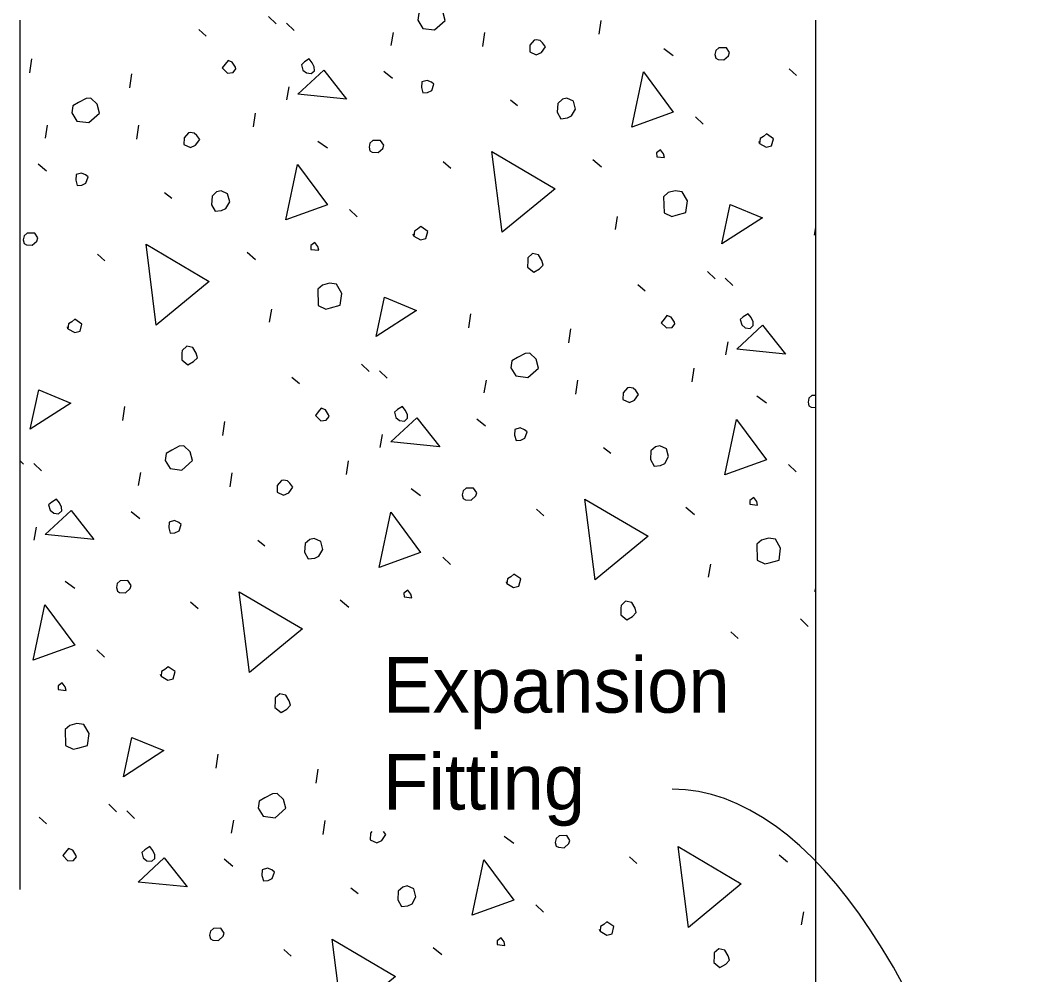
# Model space of a CAD drawing. Extents: x 0 to 30.8, y 0 to 21.2.
# Drawn here: x 22.627 to 25.369, y 14.241 to 16.841 of the extents above; entities that cross this region are included whole.
import ezdxf

# ---------------------------------------------------------------- set-up
doc = ezdxf.new("R2010")
doc.units = 0
for name, color, linetype in [('Dimension', 7, 'Continuous'), ('Miscellaneous', 7, 'Continuous'), ('SupstrConc', 7, 'Continuous')]:
    doc.layers.add(name, color=color, linetype=linetype)

msp = doc.modelspace()

# ---------------------------------------------------------------- linework, layer by layer
at = {"layer": 'Dimension'}
msp.add_ellipse((24.3864, 11.0659), major_axis=(-0.0172, -3.681), ratio=0.331804, start_param=2.220726, end_param=3.141608, dxfattribs=at)
at = {"layer": 'Miscellaneous'}
for p, q in [((23.3036, 16.8513), (23.3246, 16.8311)), ((24.2044, 16.8028), (24.2098, 16.8405)), ((23.1138, 16.816), (23.1341, 16.7981)), ((23.3524, 16.8333), (23.3734, 16.8131)), ((23.6379, 16.7726), (23.644, 16.8079)), ((23.8872, 16.7696), (23.8926, 16.8073)), ((24.3803, 16.7645), (24.4061, 16.7455)), ((22.6537, 16.6979), (22.6591, 16.7356)), ((23.6178, 16.7026), (23.6412, 16.683)), ((24.7214, 16.7084), (24.7417, 16.6906)), ((22.9261, 16.657), (22.9315, 16.6947)), ((23.3541, 16.6242), (23.3602, 16.6594)), ((23.9624, 16.6241), (23.9821, 16.6086)), ((23.2626, 16.5504), (23.268, 16.5881)), ((24.4665, 16.578), (24.4875, 16.5577)), ((22.6961, 16.5203), (22.7022, 16.5556)), ((22.9454, 16.5172), (22.9508, 16.5549)), ((23.4385, 16.5122), (23.4643, 16.4932)), ((23.7796, 16.4561), (23.8, 16.4382)), ((24.1871, 16.4617), (24.2104, 16.4421)), ((22.6761, 16.4502), (22.6994, 16.4306)), ((23.0206, 16.3717), (23.0403, 16.3563)), ((23.5247, 16.3256), (23.5457, 16.3054)), ((24.2485, 16.2711), (24.2546, 16.3064)), ((24.7909, 16.256), (24.794, 16.2778)), ((23.2453, 16.2093), (23.2687, 16.1897)), ((22.8379, 16.2037), (22.8582, 16.1859)), ((24.499, 16.1571), (24.52, 16.1368)), ((24.5479, 16.1391), (24.5688, 16.1188)), ((24.3092, 16.1217), (24.3295, 16.1039)), ((23.3067, 16.0187), (23.3128, 16.054)), ((23.8491, 16.0036), (23.8545, 16.0413)), ((24.1215, 15.9627), (24.1269, 16.0004)), ((24.5496, 15.9299), (24.5556, 15.9652)), ((23.5573, 15.9047), (23.5782, 15.8844)), ((23.6061, 15.8867), (23.627, 15.8665)), ((24.458, 15.8562), (24.4635, 15.8939)), ((23.3674, 15.8694), (23.3878, 15.8515)), ((23.8915, 15.826), (23.8976, 15.8613)), ((24.1408, 15.823), (24.1462, 15.8606)), ((24.6339, 15.8179), (24.6597, 15.7989)), ((22.9073, 15.7513), (22.9128, 15.789)), ((23.1797, 15.7104), (23.1851, 15.7481)), ((23.8715, 15.756), (23.8948, 15.7363)), ((23.6078, 15.6775), (23.6139, 15.7128)), ((24.216, 15.6775), (24.2357, 15.662)), ((22.6274, 15.6409), (22.6365, 15.6321)), ((22.6643, 15.6344), (22.6853, 15.6141)), ((23.5162, 15.6038), (23.5217, 15.6415)), ((24.7201, 15.6314), (24.7411, 15.6111)), ((22.9497, 15.5737), (22.9558, 15.609)), ((23.199, 15.5706), (23.2045, 15.6083)), ((23.6921, 15.5656), (23.7179, 15.5466)), ((22.9297, 15.5036), (22.9531, 15.484)), ((24.0333, 15.5094), (24.0536, 15.4916)), ((24.4407, 15.5151), (24.4641, 15.4955)), ((22.666, 15.4252), (22.6721, 15.4605)), ((23.2743, 15.4251), (23.2939, 15.4097)), ((23.7784, 15.379), (23.7993, 15.3588)), ((24.5021, 15.3245), (24.5082, 15.3598)), ((22.7504, 15.3132), (22.7762, 15.2942)), ((23.0915, 15.2571), (23.1118, 15.2392)), ((23.4989, 15.2627), (23.5223, 15.2431)), ((24.7527, 15.2105), (24.7737, 15.1902)), ((24.5629, 15.1751), (24.5832, 15.1573)), ((22.8366, 15.1267), (22.8575, 15.1064)), ((23.161, 14.8047), (23.1664, 14.8424)), ((23.4333, 14.7638), (23.4388, 14.8015)), ((22.8691, 14.7058), (22.8901, 14.6855)), ((22.6793, 14.6704), (22.6996, 14.6526)), ((22.918, 14.6878), (22.9389, 14.6675)), ((23.2034, 14.6271), (23.2095, 14.6624)), ((23.4527, 14.624), (23.4581, 14.6617)), ((23.9458, 14.619), (23.9716, 14.6)), ((24.2869, 14.5628), (24.3072, 14.545)), ((24.6944, 14.5685), (24.7177, 14.5489)), ((23.1833, 14.557), (23.2067, 14.5374)), ((23.5279, 14.4785), (23.5476, 14.4631)), ((24.032, 14.4324), (24.053, 14.4121)), ((24.7558, 14.3779), (24.7619, 14.4132)), ((23.7526, 14.3161), (23.776, 14.2965)), ((23.3452, 14.3105), (23.3655, 14.2926))]:
    msp.add_line(p, q, dxfattribs=at)
for points in [[(23.7101, 16.8412), (23.7238, 16.819), (23.756, 16.8147), (23.7853, 16.8406), (23.7788, 16.8648), (23.7616, 16.8809), (23.7489, 16.88), (23.7284, 16.8694), (23.7128, 16.86), (23.7101, 16.8412)], [(24.0157, 16.7729), (24.0154, 16.7547), (24.0331, 16.7466), (24.0469, 16.7528), (24.0582, 16.7688), (24.0501, 16.7796), (24.0434, 16.7855), (24.0324, 16.7878), (24.0276, 16.7865), (24.0157, 16.7729)], [(24.522, 16.7378), (24.5281, 16.7343), (24.5439, 16.7333), (24.5565, 16.7444), (24.5594, 16.753), (24.5507, 16.7662), (24.53, 16.7658), (24.5217, 16.7584), (24.5194, 16.7475), (24.522, 16.7378)], [(23.178, 16.7115), (23.1922, 16.6972), (23.2073, 16.6987), (23.2151, 16.7085), (23.2138, 16.7134), (23.2051, 16.7266), (23.1935, 16.7312), (23.1857, 16.7214), (23.178, 16.7115)], [(23.397, 16.7055), (23.4069, 16.6978), (23.4202, 16.6962), (23.4286, 16.7036), (23.4284, 16.7139), (23.4228, 16.7254), (23.4147, 16.7361), (23.4015, 16.7274), (23.3932, 16.72), (23.397, 16.7055)], [(23.3836, 16.6398), (23.4541, 16.7053), (23.5166, 16.6263), (23.3836, 16.6398)], [(24.2929, 16.5496), (24.325, 16.7005), (24.4063, 16.5903), (24.2929, 16.5496)], [(23.7205, 16.6576), (23.7244, 16.6431), (23.7371, 16.6439), (23.7485, 16.6496), (23.7543, 16.6667), (23.7475, 16.6726), (23.7359, 16.6773), (23.7214, 16.6734), (23.7205, 16.6576)], [(22.7683, 16.5888), (22.782, 16.5666), (22.8143, 16.5623), (22.8435, 16.5883), (22.8371, 16.6124), (22.8198, 16.6285), (22.8071, 16.6277), (22.7867, 16.617), (22.771, 16.6077), (22.7683, 16.5888)], [(24.0917, 16.6147), (24.0903, 16.5911), (24.1003, 16.573), (24.1179, 16.5751), (24.1293, 16.5808), (24.1399, 16.5992), (24.1341, 16.6209), (24.1163, 16.6291), (24.1043, 16.6259), (24.0917, 16.6147)], [(23.0739, 16.5206), (23.0736, 16.5024), (23.0913, 16.4942), (23.1052, 16.5005), (23.1164, 16.5165), (23.1084, 16.5272), (23.1016, 16.5332), (23.0906, 16.5354), (23.0858, 16.5341), (23.0739, 16.5206)], [(23.5802, 16.4854), (23.5864, 16.4819), (23.6022, 16.481), (23.6147, 16.4921), (23.6176, 16.5006), (23.6089, 16.5138), (23.5883, 16.5135), (23.5799, 16.5061), (23.5777, 16.4951), (23.5802, 16.4854)], [(24.6412, 16.5057), (24.6595, 16.4951), (24.674, 16.499), (24.6791, 16.5185), (24.6601, 16.5315), (24.6518, 16.5241), (24.6427, 16.5191), (24.6412, 16.5057), (24.6399, 16.5105)], [(23.94, 16.2635), (23.912, 16.4838), (24.0841, 16.3823), (23.94, 16.2635)], [(24.361, 16.4695), (24.3822, 16.4674), (24.3797, 16.4771), (24.3716, 16.4878), (24.3608, 16.4798), (24.361, 16.4695)], [(22.7787, 16.4053), (22.7826, 16.3908), (22.7953, 16.3916), (22.8067, 16.3972), (22.8125, 16.4143), (22.8057, 16.4203), (22.7941, 16.4249), (22.7796, 16.421), (22.7787, 16.4053)], [(23.3512, 16.2972), (23.3832, 16.4482), (23.4645, 16.338), (23.3512, 16.2972)], [(23.1499, 16.3624), (23.1485, 16.3387), (23.1585, 16.3207), (23.1761, 16.3228), (23.1875, 16.3284), (23.1981, 16.3468), (23.1923, 16.3686), (23.1746, 16.3767), (23.1625, 16.3735), (23.1499, 16.3624)], [(24.3798, 16.3606), (24.3811, 16.317), (24.4019, 16.307), (24.414, 16.3103), (24.4406, 16.3174), (24.4449, 16.3496), (24.4305, 16.3742), (24.4117, 16.3769), (24.3923, 16.3718), (24.3798, 16.3606)], [(24.5384, 16.2323), (24.5615, 16.3394), (24.6488, 16.3033), (24.5384, 16.2323)], [(22.6385, 16.2331), (22.6446, 16.2296), (22.6604, 16.2286), (22.6729, 16.2397), (22.6758, 16.2483), (22.6671, 16.2615), (22.6465, 16.2611), (22.6381, 16.2537), (22.6359, 16.2428), (22.6385, 16.2331)], [(23.6994, 16.2534), (23.7177, 16.2428), (23.7322, 16.2466), (23.7374, 16.2661), (23.7183, 16.2792), (23.71, 16.2717), (23.701, 16.2667), (23.6994, 16.2534), (23.6981, 16.2582)], [(23.4192, 16.2171), (23.4405, 16.2151), (23.4379, 16.2247), (23.4298, 16.2355), (23.419, 16.2274), (23.4192, 16.2171)], [(22.9982, 16.0111), (22.9702, 16.2314), (23.1423, 16.13), (22.9982, 16.0111)], [(24.0098, 16.1864), (24.0095, 16.1682), (24.0261, 16.1546), (24.0417, 16.1639), (24.0518, 16.1744), (24.0486, 16.1865), (24.0392, 16.2021), (24.0228, 16.2054), (24.0102, 16.1943), (24.0098, 16.1864)], [(23.438, 16.1083), (23.4394, 16.0646), (23.4601, 16.0547), (23.4722, 16.0579), (23.4988, 16.065), (23.5031, 16.0973), (23.4887, 16.1219), (23.4699, 16.1246), (23.4506, 16.1194), (23.438, 16.1083)], [(23.5966, 15.98), (23.6197, 16.0871), (23.707, 16.051), (23.5966, 15.98)], [(24.5925, 16.0113), (24.6023, 16.0036), (24.6157, 16.002), (24.624, 16.0094), (24.6239, 16.0197), (24.6182, 16.0311), (24.6101, 16.0419), (24.5969, 16.0332), (24.5886, 16.0258), (24.5925, 16.0113)], [(22.7576, 16.001), (22.776, 15.9904), (22.7905, 15.9943), (22.7956, 16.0138), (22.7766, 16.0268), (22.7682, 16.0194), (22.7592, 16.0144), (22.7576, 16.001), (22.7563, 16.0059)], [(24.3734, 16.0173), (24.3876, 16.003), (24.4028, 16.0044), (24.4105, 16.0143), (24.4092, 16.0191), (24.4005, 16.0323), (24.3889, 16.037), (24.3812, 16.0271), (24.3734, 16.0173)], [(24.579, 15.9456), (24.6495, 16.011), (24.7121, 15.932), (24.579, 15.9456)], [(23.068, 15.9341), (23.0677, 15.9159), (23.0843, 15.9022), (23.0999, 15.9116), (23.11, 15.9221), (23.1068, 15.9341), (23.0974, 15.9497), (23.081, 15.9531), (23.0685, 15.942), (23.068, 15.9341)], [(23.9637, 15.8946), (23.9775, 15.8724), (24.0097, 15.8681), (24.039, 15.894), (24.0325, 15.9182), (24.0152, 15.9342), (24.0025, 15.9334), (23.9821, 15.9228), (23.9665, 15.9134), (23.9637, 15.8946)], [(22.6549, 15.7276), (22.6779, 15.8347), (22.7652, 15.7986), (22.6549, 15.7276)], [(24.2693, 15.8263), (24.269, 15.8081), (24.2867, 15.7999), (24.3006, 15.8062), (24.3118, 15.8222), (24.3038, 15.833), (24.297, 15.8389), (24.286, 15.8412), (24.2812, 15.8399), (24.2693, 15.8263)], [(24.794, 15.8194), (24.7837, 15.8192), (24.7753, 15.8118), (24.7731, 15.8008), (24.7757, 15.7912)], [(23.4317, 15.7649), (23.4459, 15.7506), (23.461, 15.7521), (23.4687, 15.7619), (23.4674, 15.7668), (23.4587, 15.7799), (23.4471, 15.7846), (23.4394, 15.7748), (23.4317, 15.7649)], [(23.6507, 15.7589), (23.6605, 15.7512), (23.6739, 15.7496), (23.6823, 15.757), (23.6821, 15.7673), (23.6764, 15.7788), (23.6684, 15.7895), (23.6552, 15.7808), (23.6468, 15.7734), (23.6507, 15.7589)], [(24.7757, 15.7912), (24.7818, 15.7877), (24.794, 15.7869)], [(23.6372, 15.6932), (23.7077, 15.7587), (23.7703, 15.6797), (23.6372, 15.6932)], [(24.5466, 15.603), (24.5786, 15.7539), (24.6599, 15.6437), (24.5466, 15.603)], [(23.9741, 15.711), (23.978, 15.6965), (23.9907, 15.6973), (24.0021, 15.703), (24.0079, 15.7201), (24.0011, 15.726), (23.9895, 15.7307), (23.9751, 15.7268), (23.9741, 15.711)], [(23.022, 15.6422), (23.0357, 15.62), (23.0679, 15.6157), (23.0972, 15.6417), (23.0907, 15.6658), (23.0735, 15.6819), (23.0607, 15.6811), (23.0403, 15.6704), (23.0247, 15.6611), (23.022, 15.6422)], [(24.3454, 15.6681), (24.3439, 15.6444), (24.3539, 15.6264), (24.3715, 15.6285), (24.3829, 15.6342), (24.3935, 15.6526), (24.3877, 15.6743), (24.37, 15.6825), (24.3579, 15.6792), (24.3454, 15.6681)], [(23.3275, 15.574), (23.3272, 15.5558), (23.345, 15.5476), (23.3588, 15.5539), (23.3701, 15.5698), (23.362, 15.5806), (23.3552, 15.5866), (23.3443, 15.5888), (23.3394, 15.5875), (23.3275, 15.574)], [(23.8339, 15.5388), (23.84, 15.5353), (23.8558, 15.5344), (23.8683, 15.5455), (23.8712, 15.554), (23.8625, 15.5672), (23.8419, 15.5669), (23.8335, 15.5595), (23.8313, 15.5485), (23.8339, 15.5388)], [(22.7089, 15.5066), (22.7187, 15.4989), (22.7321, 15.4973), (22.7405, 15.5047), (22.7403, 15.515), (22.7347, 15.5264), (22.7266, 15.5372), (22.7134, 15.5285), (22.705, 15.5211), (22.7089, 15.5066)], [(24.1936, 15.3169), (24.1656, 15.5371), (24.3377, 15.4357), (24.1936, 15.3169)], [(24.6146, 15.5229), (24.6359, 15.5208), (24.6333, 15.5305), (24.6252, 15.5412), (24.6145, 15.5332), (24.6146, 15.5229)], [(22.6955, 15.4409), (22.7659, 15.5063), (22.8285, 15.4273), (22.6955, 15.4409)], [(23.6048, 15.3506), (23.6368, 15.5016), (23.7181, 15.3914), (23.6048, 15.3506)], [(23.0323, 15.4586), (23.0362, 15.4442), (23.0489, 15.445), (23.0604, 15.4506), (23.0661, 15.4677), (23.0594, 15.4737), (23.0478, 15.4783), (23.0333, 15.4744), (23.0323, 15.4586)], [(23.4036, 15.4158), (23.4022, 15.3921), (23.4122, 15.3741), (23.4297, 15.3762), (23.4411, 15.3818), (23.4517, 15.4002), (23.4459, 15.4219), (23.4282, 15.4301), (23.4161, 15.4269), (23.4036, 15.4158)], [(24.6334, 15.414), (24.6348, 15.3704), (24.6556, 15.3604), (24.6676, 15.3637), (24.6942, 15.3708), (24.6985, 15.403), (24.6842, 15.4276), (24.6653, 15.4303), (24.646, 15.4252), (24.6334, 15.414)], [(23.953, 15.3068), (23.9714, 15.2962), (23.9859, 15.3), (23.991, 15.3195), (23.972, 15.3326), (23.9636, 15.3251), (23.9546, 15.3201), (23.953, 15.3068), (23.9517, 15.3116)], [(22.8921, 15.2865), (22.8982, 15.283), (22.914, 15.282), (22.9266, 15.2931), (22.9295, 15.3017), (22.9207, 15.3149), (22.9001, 15.3145), (22.8918, 15.3071), (22.8895, 15.2962), (22.8921, 15.2865)], [(23.2518, 15.0645), (23.2239, 15.2848), (23.396, 15.1834), (23.2518, 15.0645)], [(23.6729, 15.2705), (23.6941, 15.2684), (23.6915, 15.2781), (23.6835, 15.2889), (23.6727, 15.2808), (23.6729, 15.2705)], [(24.7921, 15.2857), (24.794, 15.2949)], [(24.794, 15.287), (24.7921, 15.2857)], [(22.663, 15.0983), (22.695, 15.2492), (22.7763, 15.139), (22.663, 15.0983)], [(24.2634, 15.2398), (24.2631, 15.2216), (24.2797, 15.208), (24.2953, 15.2173), (24.3055, 15.2278), (24.3022, 15.2399), (24.2929, 15.2555), (24.2764, 15.2588), (24.2639, 15.2477), (24.2634, 15.2398)], [(23.0112, 15.0544), (23.0296, 15.0438), (23.0441, 15.0477), (23.0492, 15.0672), (23.0302, 15.0802), (23.0218, 15.0728), (23.0128, 15.0678), (23.0112, 15.0544), (23.0099, 15.0592)], [(22.7311, 15.0182), (22.7523, 15.0161), (22.7497, 15.0258), (22.7417, 15.0365), (22.7309, 15.0285), (22.7311, 15.0182)], [(23.3216, 14.9875), (23.3213, 14.9693), (23.3379, 14.9556), (23.3536, 14.965), (23.3637, 14.9754), (23.3605, 14.9875), (23.3511, 15.0031), (23.3347, 15.0065), (23.3221, 14.9954), (23.3216, 14.9875)], [(22.7499, 14.9093), (22.7512, 14.8657), (22.772, 14.8557), (22.7841, 14.859), (22.8106, 14.8661), (22.815, 14.8983), (22.8006, 14.9229), (22.7817, 14.9256), (22.7624, 14.9205), (22.7499, 14.9093)], [(22.9085, 14.781), (22.9316, 14.8881), (23.0189, 14.852), (22.9085, 14.781)], [(23.2756, 14.6956), (23.2893, 14.6734), (23.3215, 14.6691), (23.3508, 14.6951), (23.3443, 14.7192), (23.3271, 14.7353), (23.3144, 14.7345), (23.2939, 14.7238), (23.2783, 14.7145), (23.2756, 14.6956)], [(23.5812, 14.6274), (23.5809, 14.6092), (23.5986, 14.601), (23.6124, 14.6073), (23.6237, 14.6232), (23.617, 14.6322)], [(23.5854, 14.6322), (23.5812, 14.6274)], [(24.0875, 14.5922), (24.0937, 14.5887), (24.1094, 14.5877), (24.122, 14.5989), (24.1249, 14.6074), (24.1162, 14.6206), (24.0956, 14.6203), (24.0872, 14.6128), (24.0849, 14.6019), (24.0875, 14.5922)], [(22.9626, 14.56), (22.9724, 14.5522), (22.9858, 14.5507), (22.9941, 14.5581), (22.9939, 14.5684), (22.9883, 14.5798), (22.9802, 14.5906), (22.967, 14.5819), (22.9587, 14.5745), (22.9626, 14.56)], [(24.4472, 14.3703), (24.4193, 14.5905), (24.5914, 14.4891), (24.4472, 14.3703)], [(22.7435, 14.566), (22.7577, 14.5517), (22.7729, 14.5531), (22.7806, 14.563), (22.7793, 14.5678), (22.7706, 14.581), (22.759, 14.5856), (22.7512, 14.5758), (22.7435, 14.566)], [(22.9491, 14.4942), (23.0196, 14.5597), (23.0821, 14.4807), (22.9491, 14.4942)], [(23.286, 14.512), (23.2899, 14.4976), (23.3026, 14.4984), (23.314, 14.504), (23.3198, 14.5211), (23.313, 14.5271), (23.3014, 14.5317), (23.2869, 14.5278), (23.286, 14.512)], [(23.8584, 14.404), (23.8905, 14.555), (23.9718, 14.4447), (23.8584, 14.404)], [(23.6572, 14.4692), (23.6558, 14.4455), (23.6658, 14.4275), (23.6834, 14.4296), (23.6948, 14.4352), (23.7054, 14.4536), (23.6996, 14.4753), (23.6818, 14.4835), (23.6698, 14.4803), (23.6572, 14.4692)], [(23.1458, 14.3399), (23.1519, 14.3363), (23.1677, 14.3354), (23.1802, 14.3465), (23.1831, 14.3551), (23.1744, 14.3683), (23.1538, 14.3679), (23.1454, 14.3605), (23.1432, 14.3495), (23.1458, 14.3399)], [(24.2067, 14.3602), (24.225, 14.3495), (24.2395, 14.3534), (24.2446, 14.3729), (24.2256, 14.3859), (24.2173, 14.3785), (24.2083, 14.3735), (24.2067, 14.3602), (24.2054, 14.365)], [(23.9265, 14.3239), (23.9478, 14.3218), (23.9452, 14.3315), (23.9371, 14.3423), (23.9263, 14.3342), (23.9265, 14.3239)], [(23.5055, 14.1179), (23.4775, 14.3382), (23.6496, 14.2368), (23.5055, 14.1179)], [(24.5171, 14.2932), (24.5168, 14.275), (24.5334, 14.2613), (24.549, 14.2707), (24.5591, 14.2812), (24.5559, 14.2933), (24.5465, 14.3089), (24.5301, 14.3122), (24.5175, 14.3011), (24.5171, 14.2932)]]:
    msp.add_lwpolyline(points, dxfattribs=at)
at = {"layer": 'SupstrConc'}
for p, q in [((22.6273, 14.4736), (22.6273, 16.8413)), ((24.794, 13.2554), (24.794, 16.8413))]:
    msp.add_line(p, q, dxfattribs=at)

# ---------------------------------------------------------------- texts
at = {"layer": 'Dimension'}
for s, p in [('Expansion', (23.6156, 14.9554)), ('Fitting', (23.6156, 14.6914))]:
    msp.add_text(s, height=0.1512, dxfattribs=at).set_placement(p)

doc.saveas('drawing.dxf')
